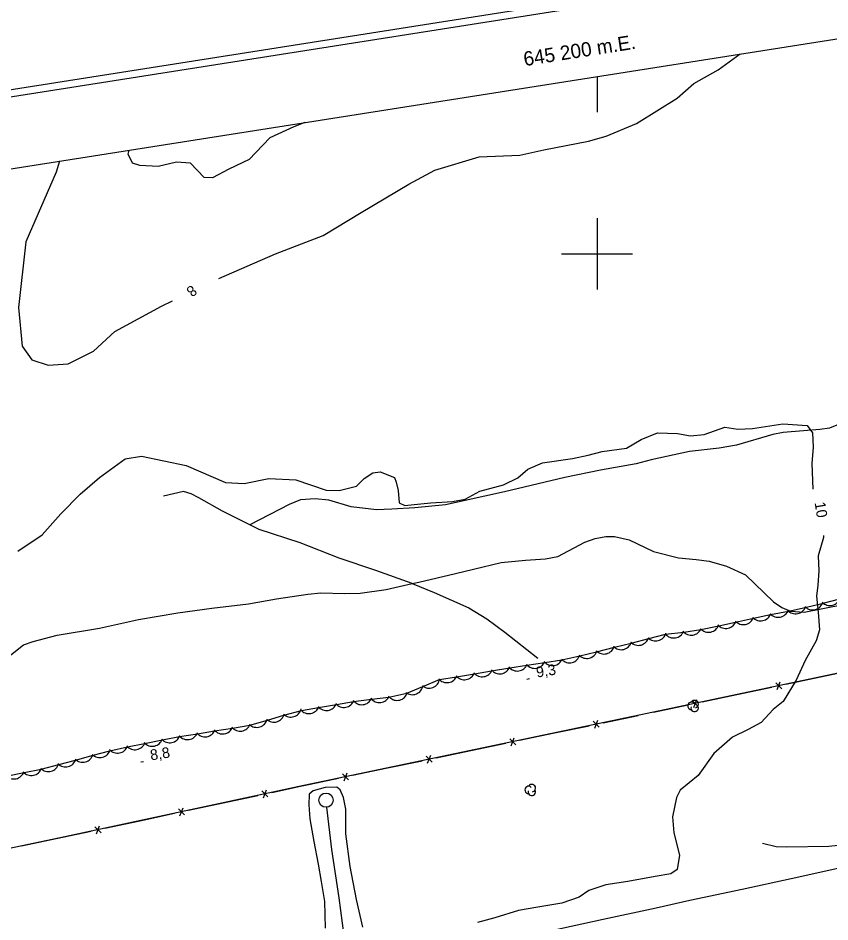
# Model space of a CAD drawing. Extents: x 643342 to 646936, y 5873857 to 5876103.
# Drawn here: x 645037.2 to 645265.5, y 5875612.3 to 5875866.3 of the extents above; entities that cross this region are included whole.
import ezdxf

# ---------------------------------------------------------------- set-up
doc = ezdxf.new("R2010")
doc.units = 0
for name, color, linetype in [('Niveau 1', 7, 'Continuous'), ('Niveau 2', 7, 'Continuous'), ('Niveau 22', 7, 'Continuous'), ('Niveau 25', 7, 'Continuous'), ('Niveau 3', 7, 'Continuous'), ('Niveau 36', 7, 'Continuous'), ('Niveau 37', 7, 'Continuous'), ('Niveau 4', 7, 'Continuous'), ('Niveau 44', 7, 'Continuous'), ('Niveau 60', 7, 'Continuous'), ('Niveau 61', 7, 'Continuous')]:
    doc.layers.add(name, color=color, linetype=linetype)

msp = doc.modelspace()

# ---------------------------------------------------------------- linework, layer by layer
at = {"layer": 'Niveau 1'}
for points in [[(645095.55, 5875735.71), (645100.83, 5875735.46), (645107.7, 5875736.86), (645115.31, 5875736.46), (645123.85, 5875733.56), (645127.47, 5875733.46), (645132.42, 5875734.76), (645134.51, 5875736.87), (645136.93, 5875738.48), (645139.06, 5875738.77), (645143.1, 5875737.19), (645143.57, 5875735.83), (645144.13, 5875733.54), (645144.38, 5875730.05), (645145.96, 5875729.31), (645148.61, 5875729.6), (645153.29, 5875730), (645159.37, 5875730.4), (645162.92, 5875731.05), (645167.03, 5875733.33), (645173.74, 5875735.07), (645177.69, 5875737.1), (645180.51, 5875739.5), (645184.66, 5875741.26), (645193.1, 5875742.5), (645197.55, 5875743.41), (645201.41, 5875744.49), (645208.31, 5875745.37), (645212.39, 5875747.88), (645217, 5875749.67), (645222.65, 5875749.51), (645226.26, 5875748.83), (645230.11, 5875749.27), (645235.97, 5875751.29), (645239.56, 5875750.78), (645243.73, 5875750.96), (645252.21, 5875752.2), (645259.04, 5875751.79), (645260.56, 5875749.71), (645260.75, 5875745.64), (645260.34, 5875741.06), (645260.69, 5875733.85)], [(645037.18, 5875716.46), (645044.03, 5875721.02), (645049.22, 5875726.97), (645054.7, 5875732.46), (645060.12, 5875737.14), (645067.36, 5875742.43), (645071.91, 5875743.11), (645084.51, 5875740.56), (645095.55, 5875735.71)], [(645263.68, 5875720.87), (645263.7, 5875720.29), (645262.12, 5875715.14), (645262.38, 5875710.9), (645262.04, 5875706.9), (645261.68, 5875703.84), (645262.19, 5875699.33), (645262.58, 5875694.35), (645261.63, 5875691.29), (645258.47, 5875685.71), (645255.94, 5875680.18), (645252.29, 5875674.2), (645249.47, 5875671.98), (645246.13, 5875668.3), (645242.47, 5875666.35), (645238.07, 5875664.22), (645232.84, 5875659.62), (645228.39, 5875653.4), (645223.35, 5875649.34), (645222.31, 5875647.27), (645221.23, 5875641.8), (645221.63, 5875637.28), (645223.17, 5875630.99), (645222.48, 5875627.02), (645220.73, 5875625.81), (645216.38, 5875625.03), (645208.7, 5875623.66), (645202.45, 5875622.71), (645197.7, 5875621.13), (645195.02, 5875619.2), (645190.1, 5875617.54), (645183.33, 5875616.43), (645177.89, 5875615.49), (645171.31, 5875613.45)], [(645134.2, 5875610.81), (645132.4, 5875618.6), (645130.64, 5875627.87), (645129.37, 5875636.99), (645129.39, 5875643.96), (645128.7, 5875647.23), (645127.75, 5875649.37), (645126.87, 5875650.11), (645123.61, 5875650), (645120.2, 5875649.07), (645119.05, 5875648.15), (645118.97, 5875645.16), (645119.31, 5875641.27), (645120.4, 5875634.87), (645121.61, 5875628.49), (645122.45, 5875623.59), (645123.36, 5875617.99), (645123.55, 5875610.52)], [(645171.31, 5875613.45), (645166.42, 5875612.09)]]:
    msp.add_lwpolyline(points, dxfattribs=at)
at = {"layer": 'Niveau 2'}
for points in [[(645093.67, 5875793.09), (645109.59, 5875800.04), (645122.99, 5875805.13), (645133.7, 5875811.63), (645147.06, 5875819.63), (645154.38, 5875823.51), (645166.84, 5875827.24), (645178.29, 5875827.73), (645185.01, 5875829.23), (645197.57, 5875831.68), (645202.55, 5875833.09), (645211.06, 5875836.6), (645222.48, 5875843.79), (645227.22, 5875847.85), (645234.01, 5875851.74), (645240.19, 5875856.18)], [(645117.88, 5875836.93), (645114.76, 5875835.73), (645108, 5875832.6), (645102.21, 5875826.52), (645096.47, 5875823.77), (645091.91, 5875821.35), (645089.58, 5875821.45), (645085.74, 5875825.49), (645081.75, 5875825.8), (645076.63, 5875824.55), (645071.43, 5875824.82), (645069.39, 5875825.52), (645068.24, 5875828.04), (645068.45, 5875829.16)], [(645048.93, 5875826.09), (645047.92, 5875822.98), (645039.39, 5875803.35), (645037.4, 5875784.96), (645038.37, 5875774.06), (645041.16, 5875770.21), (645045.72, 5875768.73), (645051.29, 5875769.08), (645058.44, 5875772.61), (645064.47, 5875778.14), (645077.59, 5875785.32), (645080.65, 5875786.79)]]:
    msp.add_lwpolyline(points, dxfattribs=at)
at = {"layer": 'Niveau 22'}
for points in [[(645272.1, 5875753.71), (645265.37, 5875751.04), (645262.62, 5875750.69), (645252.36, 5875749.81), (645249.4, 5875749.21), (645239.21, 5875746.24), (645234.3, 5875745.36), (645226.01, 5875744.42), (645215.18, 5875742.1), (645210.97, 5875741.04), (645201.01, 5875739.25), (645190.96, 5875737.11), (645173.98, 5875733.09), (645157.42, 5875729.46), (645148.76, 5875728.61), (645142.27, 5875728.29), (645137.98, 5875728.04), (645130.91, 5875728.95), (645124.57, 5875730.75), (645120.8, 5875731.13), (645116.63, 5875730.89), (645113.48, 5875729.57), (645102.35, 5875723.84)], [(645148.07, 5875707.36), (645137.84, 5875711.05), (645127.51, 5875714.49), (645116.52, 5875718.81), (645104.99, 5875722.5), (645102.35, 5875723.84), (645094.73, 5875727.71), (645088.1, 5875731.47), (645085.9, 5875732.57), (645083.74, 5875733.2), (645078.14, 5875731.91)], [(645033.33, 5875685.84), (645038.8, 5875690.18), (645041.52, 5875691.11), (645048.27, 5875692.86), (645060.14, 5875694.82), (645071.14, 5875697.28), (645082.19, 5875699.17), (645091.76, 5875700.46), (645102.04, 5875701.69), (645109.86, 5875703.06), (645118.72, 5875704.4), (645122.31, 5875704.71), (645128.97, 5875704.58), (645133.4, 5875704.61), (645140.76, 5875705.71), (645148.07, 5875707.36), (645149.9, 5875707.78), (645160.17, 5875710.18), (645165.3, 5875711.43), (645173.06, 5875713.27), (645179.87, 5875713.97), (645185.54, 5875714.33), (645188.97, 5875714.98), (645196.53, 5875719.01), (645199.47, 5875719.97), (645202.44, 5875720.57), (645204.88, 5875720.55), (645209.04, 5875719.62), (645215.84, 5875716.34), (645222.86, 5875714.61), (645227.9, 5875714.11), (645231.55, 5875713.6), (645236.43, 5875712.27), (645241.76, 5875709.81), (645249.64, 5875702.2), (645251.99, 5875700.65), (645254.41, 5875699.57), (645258.26, 5875699.32), (645269.22, 5875701.43)], [(645148.07, 5875707.36), (645154.24, 5875704.85), (645163.94, 5875700.54), (645168.99, 5875697.47), (645174.1, 5875693.7), (645183.36, 5875686.43)], [(645130.33, 5875597.64), (645127.47, 5875619.01), (645125.49, 5875632.65), (645124.08, 5875644.49)]]:
    msp.add_lwpolyline(points, dxfattribs=at)
at = {"layer": 'Niveau 25'}
msp.add_lwpolyline([(645179.92, 5875608.25), (645201.72, 5875613.07), (645216.66, 5875616.24), (645226.12, 5875618.34), (645240.82, 5875621.49), (645254.6, 5875624.44), (645271.1, 5875628.09)], dxfattribs=at)
at = {"layer": 'Niveau 3'}
for p, q in [((645180.27, 5875680.52), (645181.06, 5875680.65)), ((645071.75, 5875657.23), (645072.54, 5875657.35))]:
    msp.add_line(p, q, dxfattribs=at)
at = {"layer": 'Niveau 36'}
msp.add_circle((645123.81, 5875646.49), 2, dxfattribs=at)
at = {"layer": 'Niveau 37'}
for p, q in [((645305.77, 5875690.21), (645215.86, 5875671.2)), ((645215.86, 5875671.2), (645117.57, 5875650.61))]:
    msp.add_line(p, q, dxfattribs=at)
for points in [[(645262.82, 5875681.13), (645272.6, 5875683.2)], [(645250.25, 5875679.49), (645251.93, 5875677.81)], [(645250.66, 5875677.54), (645251.52, 5875679.76)], [(645253.04, 5875679.06), (645262.82, 5875681.13)], [(645239.34, 5875676.17), (645249.12, 5875678.23)], [(645226.77, 5875674.53), (645228.45, 5875672.84)], [(645227.18, 5875672.57), (645228.04, 5875674.8)], [(645229.56, 5875674.1), (645239.34, 5875676.17)], [(645215.86, 5875671.2), (645225.65, 5875673.27)], [(645201.74, 5875668.24), (645211.53, 5875670.29)], [(645188.04, 5875665.37), (645197.83, 5875667.42)], [(645198.95, 5875668.68), (645200.64, 5875666.99)], [(645199.36, 5875666.72), (645200.23, 5875668.95)], [(645175.87, 5875661.8), (645176.74, 5875664.03)], [(645178.25, 5875663.32), (645188.04, 5875665.37)], [(645164.55, 5875660.45), (645174.34, 5875662.5)], [(645175.46, 5875663.76), (645177.15, 5875662.07)], [(645151.97, 5875658.84), (645153.66, 5875657.15)], [(645152.38, 5875656.88), (645153.25, 5875659.11)], [(645154.76, 5875658.4), (645164.55, 5875660.45)], [(645141.06, 5875655.53), (645150.85, 5875657.58)], [(645128.48, 5875653.92), (645130.17, 5875652.23)], [(645128.89, 5875651.96), (645129.76, 5875654.19)], [(645131.27, 5875653.48), (645141.06, 5875655.53)], [(645117.57, 5875650.61), (645127.36, 5875652.66)], [(645117.57, 5875650.61), (645049.07, 5875635.9), (644963.02, 5875617.79), (644871.7, 5875598.49), (644797.33, 5875582.76), (644750.3, 5875572.83), (644759.41, 5875529.24), (644766.72, 5875494.89)], [(645105.8, 5875649.11), (645107.49, 5875647.43)], [(645106.22, 5875647.15), (645107.07, 5875649.38)], [(645108.59, 5875648.68), (645118.37, 5875650.78)], [(645094.9, 5875645.74), (645104.68, 5875647.84)], [(645082.34, 5875644.07), (645084.03, 5875642.39)], [(645082.76, 5875642.11), (645083.61, 5875644.34)], [(645085.13, 5875643.64), (645094.9, 5875645.74)], [(645071.44, 5875640.7), (645081.22, 5875642.8)], [(645058.87, 5875639.03), (645060.56, 5875637.35)], [(645059.29, 5875637.07), (645060.14, 5875639.3)], [(645061.66, 5875638.6), (645071.44, 5875640.7)], [(645047.98, 5875635.67), (645057.75, 5875637.76)], [(645038.19, 5875633.61), (645047.98, 5875635.67)]]:
    msp.add_lwpolyline(points, dxfattribs=at)
at = {"layer": 'Niveau 4'}
msp.add_lwpolyline([(645273.92, 5875634.38), (645265.18, 5875633.51), (645253.24, 5875633.29), (645250.32, 5875633.38), (645246.52, 5875634.34)], dxfattribs=at)
at = {"layer": 'Niveau 44'}
msp.add_lwpolyline([(645033.9, 5875653.22), (645038.95, 5875654.22), (645043.71, 5875655.17), (645048.7, 5875656.48), (645053.38, 5875657.76), (645058.35, 5875659.1), (645063.04, 5875660.37), (645068.04, 5875661.46), (645072.81, 5875662.41), (645077.85, 5875663.41), (645082.61, 5875664.36), (645087.69, 5875665.15), (645092.48, 5875665.93), (645097.56, 5875666.74), (645102.35, 5875667.52), (645107.32, 5875668.99), (645111.96, 5875670.4), (645116.92, 5875671.64), (645121.7, 5875672.49), (645126.76, 5875673.39), (645131.54, 5875674.24), (645136.64, 5875674.87), (645141.45, 5875675.46), (645146.5, 5875676.6), (645151.02, 5875678.38), (645155.72, 5875680.37), (645160.51, 5875681.17), (645165.58, 5875682.01), (645170.37, 5875682.81), (645175.44, 5875683.65), (645180.24, 5875684.4), (645185.33, 5875685.18), (645190.12, 5875685.93), (645195.17, 5875687.01), (645199.88, 5875688.2), (645204.87, 5875689.46), (645209.57, 5875690.65), (645214.56, 5875691.92), (645219.27, 5875693.11), (645224.37, 5875693.71), (645229.16, 5875694.47), (645234.22, 5875695.49), (645238.96, 5875696.53), (645243.99, 5875697.62), (645248.73, 5875698.66), (645253.78, 5875699.64), (645258.54, 5875700.6), (645263.53, 5875701.88), (645268.24, 5875703.08)], dxfattribs=at)
for centre, radius, start, end in [((645260.6, 5875702.96), 3, 224.3117, 344.2896), ((645260.6, 5875702.96), 3, 224.3117, 344.2896), ((645260.6, 5875702.96), 3, 224.3117, 344.2896), ((645265.45, 5875704.19), 3, 224.3117, 344.2896), ((645265.45, 5875704.19), 3, 224.3117, 344.2896), ((645265.45, 5875704.19), 3, 224.3117, 344.2896), ((645250.91, 5875700.87), 3, 221.3693, 341.3473), ((645250.91, 5875700.87), 3, 221.3693, 341.3473), ((645250.91, 5875700.87), 3, 221.3693, 341.3473), ((645255.81, 5875701.85), 3, 221.3693, 341.3473), ((645255.81, 5875701.85), 3, 221.3693, 341.3473), ((645255.81, 5875701.85), 3, 221.3693, 341.3473), ((645241.1, 5875698.8), 3, 222.3344, 342.3124), ((645241.1, 5875698.8), 3, 222.3344, 342.3124), ((645241.1, 5875698.8), 3, 222.3344, 342.3124), ((645245.98, 5875699.86), 3, 222.3344, 342.3124), ((645245.98, 5875699.86), 3, 222.3344, 342.3124), ((645245.98, 5875699.86), 3, 222.3344, 342.3124), ((645226.49, 5875695.83), 3, 218.9316, 338.9095), ((645226.49, 5875695.83), 3, 218.9316, 338.9095), ((645226.49, 5875695.83), 3, 218.9316, 338.9095), ((645231.33, 5875696.67), 3, 222.3344, 342.3124), ((645231.33, 5875696.67), 3, 222.3344, 342.3124), ((645231.33, 5875696.67), 3, 222.3344, 342.3124), ((645236.21, 5875697.73), 3, 222.3344, 342.3124), ((645236.21, 5875697.73), 3, 222.3344, 342.3124), ((645236.21, 5875697.73), 3, 222.3344, 342.3124), ((645211.63, 5875692.99), 3, 224.2312, 344.2092), ((645211.63, 5875692.99), 3, 224.2312, 344.2092), ((645211.63, 5875692.99), 3, 224.2312, 344.2092), ((645216.48, 5875694.22), 3, 224.2312, 344.2092), ((645216.48, 5875694.22), 3, 224.2312, 344.2092), ((645216.48, 5875694.22), 3, 224.2312, 344.2092), ((645221.55, 5875695.06), 3, 218.9316, 338.9095), ((645221.55, 5875695.06), 3, 218.9316, 338.9095), ((645221.55, 5875695.06), 3, 218.9316, 338.9095), ((645201.94, 5875690.54), 3, 224.2312, 344.2092), ((645201.94, 5875690.54), 3, 224.2312, 344.2092), ((645201.94, 5875690.54), 3, 224.2312, 344.2092), ((645206.79, 5875691.77), 3, 224.2312, 344.2092), ((645206.79, 5875691.77), 3, 224.2312, 344.2092), ((645206.79, 5875691.77), 3, 224.2312, 344.2092), ((645192.25, 5875688.08), 3, 224.2312, 344.2092), ((645192.25, 5875688.08), 3, 224.2312, 344.2092), ((645192.25, 5875688.08), 3, 224.2312, 344.2092), ((645197.09, 5875689.31), 3, 224.2312, 344.2092), ((645197.09, 5875689.31), 3, 224.2312, 344.2092), ((645197.09, 5875689.31), 3, 224.2312, 344.2092), ((645177.57, 5875685.77), 3, 218.8199, 338.7979), ((645177.57, 5875685.77), 3, 218.8199, 338.7979), ((645177.57, 5875685.77), 3, 218.8199, 338.7979), ((645182.51, 5875686.53), 3, 218.8199, 338.7979), ((645182.51, 5875686.53), 3, 218.8199, 338.7979), ((645182.51, 5875686.53), 3, 218.8199, 338.7979), ((645187.45, 5875687.3), 3, 218.8199, 338.7979), ((645187.45, 5875687.3), 3, 218.8199, 338.7979), ((645187.45, 5875687.3), 3, 218.8199, 338.7979), ((645162.75, 5875683.33), 3, 219.4895, 339.4675), ((645162.75, 5875683.33), 3, 219.4895, 339.4675), ((645162.75, 5875683.33), 3, 219.4895, 339.4675), ((645167.69, 5875684.15), 3, 219.4895, 339.4675), ((645167.69, 5875684.15), 3, 219.4895, 339.4675), ((645167.69, 5875684.15), 3, 219.4895, 339.4675), ((645172.62, 5875684.98), 3, 219.4895, 339.4675), ((645172.62, 5875684.98), 3, 219.4895, 339.4675), ((645172.62, 5875684.98), 3, 219.4895, 339.4675), ((645152.77, 5875680.96), 3, 231.4559, 351.4339), ((645152.77, 5875680.96), 3, 231.4559, 351.4339), ((645152.77, 5875680.96), 3, 231.4559, 351.4339), ((645157.82, 5875682.51), 3, 219.4895, 339.4675), ((645157.82, 5875682.51), 3, 219.4895, 339.4675), ((645157.82, 5875682.51), 3, 219.4895, 339.4675), ((645148.11, 5875679.13), 3, 231.4559, 351.4339), ((645148.11, 5875679.13), 3, 231.4559, 351.4339), ((645148.11, 5875679.13), 3, 231.4559, 351.4339), ((645128.84, 5875675.55), 3, 220.0839, 340.0619), ((645128.84, 5875675.55), 3, 220.0839, 340.0619), ((645128.84, 5875675.55), 3, 220.0839, 340.0619), ((645133.87, 5875676.3), 3, 216.9959, 336.9738), ((645133.87, 5875676.3), 3, 216.9959, 336.9738), ((645133.87, 5875676.3), 3, 216.9959, 336.9738), ((645138.83, 5875676.91), 3, 216.9959, 336.9738), ((645138.83, 5875676.91), 3, 216.9959, 336.9738), ((645138.83, 5875676.91), 3, 216.9959, 336.9738), ((645143.79, 5875677.52), 3, 216.9959, 336.9738), ((645143.79, 5875677.52), 3, 216.9959, 336.9738), ((645143.79, 5875677.52), 3, 216.9959, 336.9738), ((645227.44, 5875673.48), 1.05, 282.2692, 149.7263), ((645113.92, 5875672.83), 3, 226.7944, 346.7724), ((645113.92, 5875672.83), 3, 226.7944, 346.7724), ((645113.92, 5875672.83), 3, 226.7944, 346.7724), ((645119, 5875673.81), 3, 220.0839, 340.0619), ((645119, 5875673.81), 3, 220.0839, 340.0619), ((645119, 5875673.81), 3, 220.0839, 340.0619), ((645123.92, 5875674.68), 3, 220.0839, 340.0619), ((645123.92, 5875674.68), 3, 220.0839, 340.0619), ((645123.92, 5875674.68), 3, 220.0839, 340.0619), ((645226.54, 5875672.95), 1.05, 44.1154, 269.804), ((645227.44, 5875672.43), 1.05, 166.9369, 29.6212), ((645104.34, 5875669.94), 3, 226.7944, 346.7724), ((645104.34, 5875669.94), 3, 226.7944, 346.7724), ((645104.34, 5875669.94), 3, 226.7944, 346.7724), ((645109.13, 5875671.38), 3, 226.7944, 346.7724), ((645109.13, 5875671.38), 3, 226.7944, 346.7724), ((645109.13, 5875671.38), 3, 226.7944, 346.7724), ((645094.74, 5875668.08), 3, 219.1602, 339.1381), ((645094.74, 5875668.08), 3, 219.1602, 339.1381), ((645094.74, 5875668.08), 3, 219.1602, 339.1381), ((645099.68, 5875668.87), 3, 219.1602, 339.1381), ((645099.68, 5875668.87), 3, 219.1602, 339.1381), ((645099.68, 5875668.87), 3, 219.1602, 339.1381), ((645079.89, 5875665.61), 3, 221.2649, 341.2428), ((645079.89, 5875665.61), 3, 221.2649, 341.2428), ((645079.89, 5875665.61), 3, 221.2649, 341.2428), ((645084.87, 5875666.49), 3, 219.1602, 339.1381), ((645084.87, 5875666.49), 3, 219.1602, 339.1381), ((645084.87, 5875666.49), 3, 219.1602, 339.1381), ((645089.8, 5875667.28), 3, 219.1602, 339.1381), ((645089.8, 5875667.28), 3, 219.1602, 339.1381), ((645089.8, 5875667.28), 3, 219.1602, 339.1381), ((645065.18, 5875662.69), 3, 221.2649, 341.2428), ((645065.18, 5875662.69), 3, 221.2649, 341.2428), ((645065.18, 5875662.69), 3, 221.2649, 341.2428), ((645070.08, 5875663.66), 3, 221.2649, 341.2428), ((645070.08, 5875663.66), 3, 221.2649, 341.2428), ((645070.08, 5875663.66), 3, 221.2649, 341.2428), ((645074.98, 5875664.64), 3, 221.2649, 341.2428), ((645074.98, 5875664.64), 3, 221.2649, 341.2428), ((645074.98, 5875664.64), 3, 221.2649, 341.2428), ((645055.41, 5875660.13), 3, 225.1677, 345.1456), ((645055.41, 5875660.13), 3, 225.1677, 345.1456), ((645055.41, 5875660.13), 3, 225.1677, 345.1456), ((645060.23, 5875661.43), 3, 225.1677, 345.1456), ((645060.23, 5875661.43), 3, 225.1677, 345.1456), ((645060.23, 5875661.43), 3, 225.1677, 345.1456), ((645045.75, 5875657.52), 3, 225.1677, 345.1456), ((645045.75, 5875657.52), 3, 225.1677, 345.1456), ((645045.75, 5875657.52), 3, 225.1677, 345.1456), ((645050.58, 5875658.82), 3, 225.1677, 345.1456), ((645050.58, 5875658.82), 3, 225.1677, 345.1456), ((645050.58, 5875658.82), 3, 225.1677, 345.1456), ((645036.08, 5875655.45), 3, 221.2124, 341.1903), ((645036.08, 5875655.45), 3, 221.2124, 341.1903), ((645036.08, 5875655.45), 3, 221.2124, 341.1903), ((645040.98, 5875656.42), 3, 221.2124, 341.1903), ((645040.98, 5875656.42), 3, 221.2124, 341.1903), ((645040.98, 5875656.42), 3, 221.2124, 341.1903), ((645180.77, 5875649.35), 1.05, 44.1154, 269.804), ((645181.67, 5875648.83), 1.05, 166.9369, 29.6212), ((645181.67, 5875649.88), 1.05, 282.2692, 149.7263)]:
    msp.add_arc(centre, radius, start, end, dxfattribs=at)
at = {"layer": 'Niveau 60'}
msp.add_line((645200, 5875849.85), (645200, 5875839.85), dxfattribs=at)
for points in [[(643342.09, 5875579.85), (646664.86, 5876102.57), (646935.9, 5874379.74), (643613.15, 5873856.99), (643342.1, 5875579.83)], [(643342.09, 5875579.85), (646664.86, 5876102.57), (646935.9, 5874379.74), (643613.15, 5873856.99), (643342.1, 5875579.83)], [(643342.09, 5875579.85), (646664.86, 5876102.57), (646935.9, 5874379.74), (643613.15, 5873856.99), (643342.1, 5875579.83)], [(643344.38, 5875578.18), (646663.19, 5876100.29), (646933.6, 5874381.38), (643614.81, 5873859.28), (643344.38, 5875578.18)], [(643344.38, 5875578.18), (646663.19, 5876100.29), (646933.6, 5874381.38), (643614.81, 5873859.28), (643344.38, 5875578.18)], [(643344.38, 5875578.18), (646663.19, 5876100.29), (646933.6, 5874381.38), (643614.81, 5873859.28), (643344.38, 5875578.18)]]:
    msp.add_lwpolyline(points, dxfattribs=at)
msp.add_lwpolyline([(643367.26, 5875561.52), (646133.22, 5875996.67), (646397.42, 5874317.29), (643631.46, 5873882.15)], close=True, dxfattribs=at)
at = {"layer": 'Niveau 61'}
for points in [[(645200, 5875810), (645200, 5875800), (645200, 5875790)], [(645190, 5875800), (645200, 5875800), (645210, 5875800)]]:
    msp.add_lwpolyline(points, dxfattribs=at)

# ---------------------------------------------------------------- texts
at = {"layer": 'Niveau 1'}
msp.add_text('10', height=3, rotation=279.109, dxfattribs=at).set_placement((645261.15, 5875730.08))
at = {"layer": 'Niveau 2'}
msp.add_text('8', height=3, rotation=219.2618, dxfattribs=at).set_placement((645085.99, 5875791.41))
at = {"layer": 'Niveau 3'}
for s, p in [('9,3  ', (645183.12, 5875680.93)), ('8,8  ', (645074.61, 5875657.64))]:
    msp.add_text(s, height=3, rotation=8.941, dxfattribs=at).set_placement(p)
at = {"layer": 'Niveau 61'}
msp.add_text('645 200 m.E.', height=3.9998, rotation=8.9407, dxfattribs=at).set_placement((645179.65, 5875852.74))

doc.saveas('drawing.dxf')
